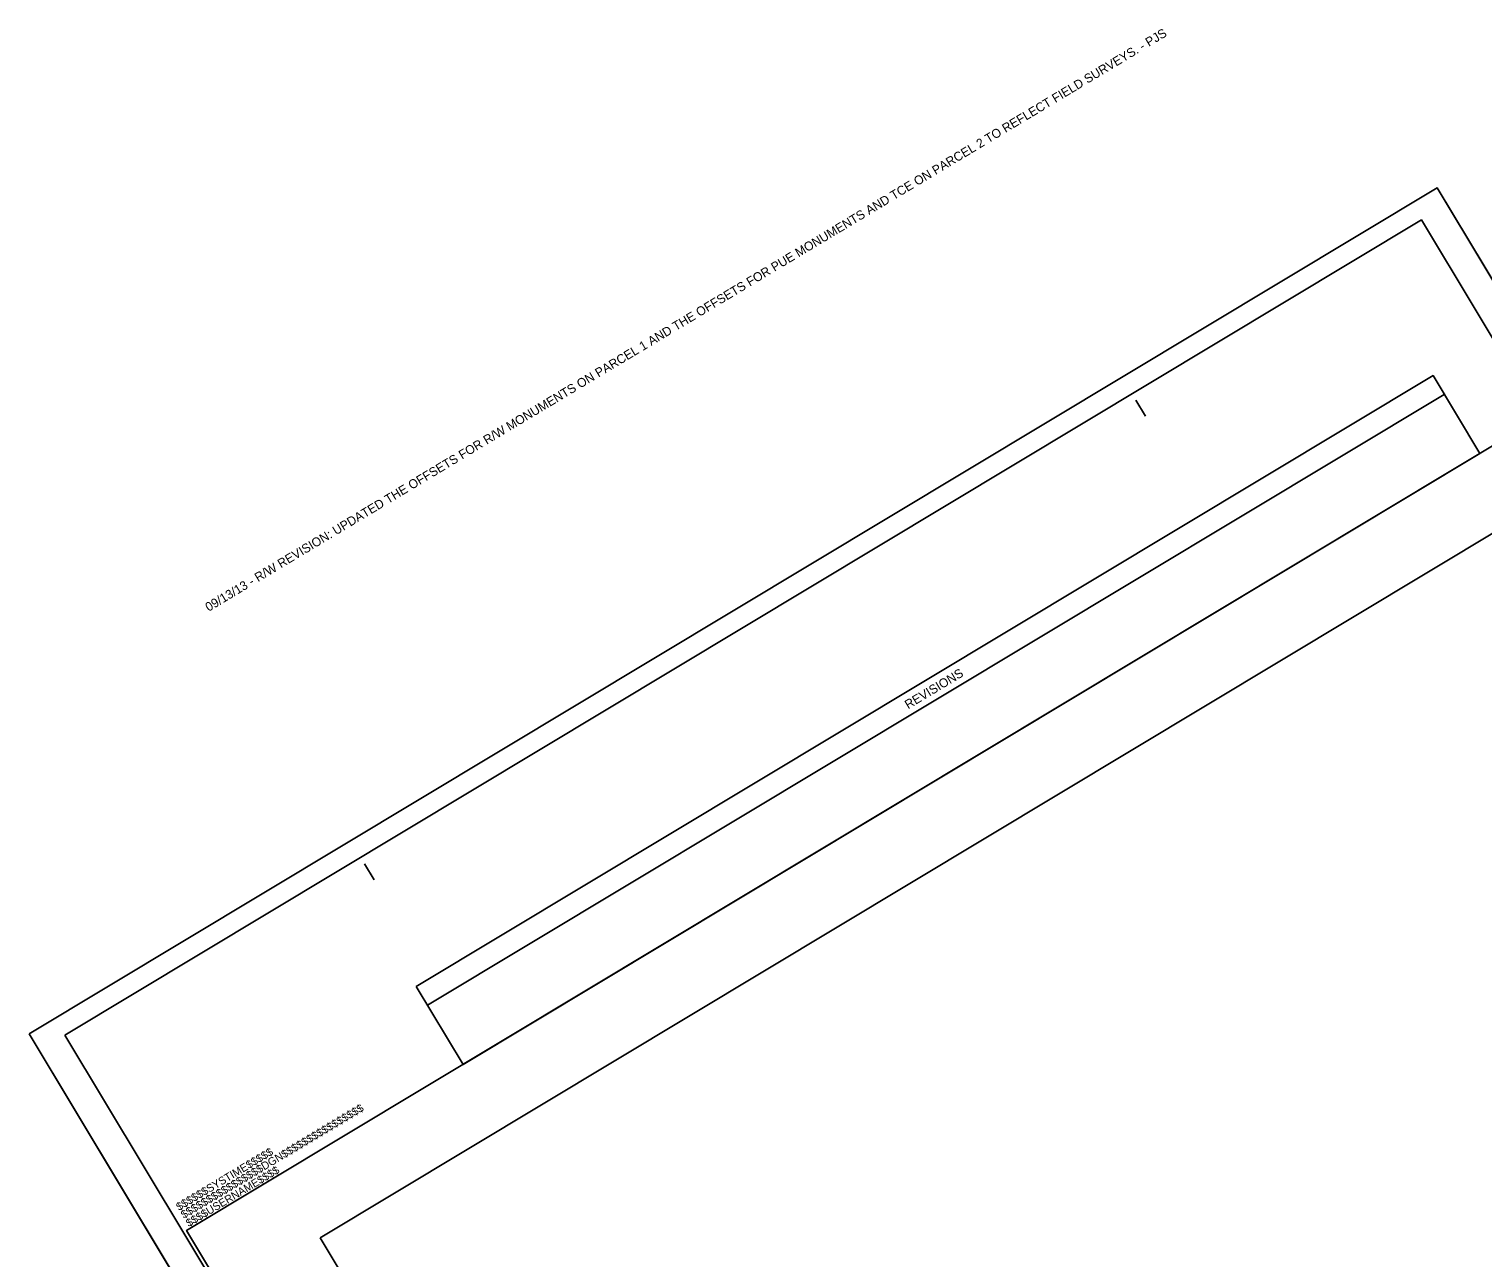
# Model space of a CAD drawing. Extents: x 1779635 to 1781473, y 814562 to 816692.
# Drawn here: x 1779635 to 1780604, y 815873 to 816692 of the extents above; entities that cross this region are included whole.
import ezdxf

# ---------------------------------------------------------------- set-up
doc = ezdxf.new("R2010")
doc.units = 0
for name, color, linetype in [('Sheet Block Revision CELL', 7, 'Continuous'), ('Sheet Clip Boundary CELL', 7, 'Continuous'), ('Sheet Cutting Line CELL', 7, 'Continuous'), ('Sheet Plan CELL', 7, 'Continuous'), ('Sheet Plan Layout CELL', 7, 'Continuous'), ('Sheet Plot Border Inside CELL', 7, 'Continuous'), ('Sheet Plot Border Outside CELL', 7, 'Continuous')]:
    doc.layers.add(name, color=color, linetype=linetype)

msp = doc.modelspace()

# ---------------------------------------------------------------- linework, layer by layer
at = {"layer": 'Sheet Block Revision CELL'}
msp.add_line((1779900.54, 816041.56), (1780578.24, 816448.78), dxfattribs=at)
msp.add_lwpolyline([(1779893.02, 816054.02), (1780570.74, 816461.24), (1780601.94, 816409.36), (1779924.22, 816002.14)], close=True, dxfattribs=at)
at = {"layer": 'Sheet Clip Boundary CELL'}
msp.add_lwpolyline([(1779828.88, 815886.54), (1780515.2, 814744.31), (1781170.74, 815138.2), (1781108.01, 815242.61), (1781289.29, 815351.54), (1780665.7, 816389.35)], close=True, dxfattribs=at)
at = {"layer": 'Sheet Cutting Line CELL'}
for p, q in [((1780573.48, 816586.5), (1779634.88, 816022.53)), ((1781440.55, 815143.46), (1780573.48, 816586.5)), ((1779634.88, 816022.53), (1780501.95, 814579.49))]:
    msp.add_line(p, q, dxfattribs=at)
at = {"layer": 'Sheet Plan CELL'}
for p, q in [((1780372.73, 816444.89), (1780379.19, 816434.18)), ((1779858.45, 816135.85), (1779864.88, 816125.13)), ((1779739.93, 815891.42), (1779739.93, 815891.42))]:
    msp.add_line(p, q, dxfattribs=at)
for points in [[(1779739.93, 815891.42), (1780639.92, 816432.22), (1781309.49, 815317.93), (1781180.87, 815240.63), (1781283.89, 815069.16), (1780512.49, 814605.66)], [(1781412.53, 815146.43), (1780639.95, 816432.21), (1779739.93, 815891.42), (1780512.49, 814605.66)]]:
    msp.add_lwpolyline(points, close=True, dxfattribs=at)
at = {"layer": 'Sheet Plan Layout CELL'}
msp.add_lwpolyline([(1780639.92, 816432.22), (1779739.93, 815891.42), (1780512.48, 814605.67), (1781231.23, 815037.54), (1781108.01, 815242.61), (1781289.29, 815351.54)], close=True, dxfattribs=at)
at = {"layer": 'Sheet Plot Border Inside CELL'}
msp.add_lwpolyline([(1779658.72, 816021.69), (1780516.78, 814593.67), (1781421.08, 815137.02), (1780563.03, 816565.06)], close=True, dxfattribs=at)
at = {"layer": 'Sheet Plot Border Outside CELL'}
msp.add_lwpolyline([(1779634.88, 816022.53), (1780501.95, 814579.49), (1781440.55, 815143.46), (1780573.48, 816586.5)], close=True, dxfattribs=at)

# ---------------------------------------------------------------- texts
at = {"layer": 'Sheet Block Revision CELL'}
for s, p in [('09/13/13 - R/W REVISION: UPDATED THE OFFSETS FOR R/W MONUMENTS ON PARCEL 1 AND THE OFFSETS FOR PUE MONUMENTS AND TCE ON PARCEL 2 TO REFLECT FIELD SURVEYS. - PJS', (1779754.6, 816303.78)), ('REVISIONS', (1780220.87, 816238.77))]:
    msp.add_text(s, height=6, rotation=31, dxfattribs=at).set_placement(p)
at = {"layer": 'Sheet Plan CELL'}
for s, p in [('$$$$$$$$$$$$$$$$DGN$$$$$$$$$$$$$$$$', (1779738.02, 815899.18)), ('$$$$$$SYSTIME$$$$$', (1779734.87, 815904.38)), ('$$$$USERNAME$$$$', (1779741.4, 815893.58))]:
    msp.add_text(s, height=5.25, rotation=31, dxfattribs=at).set_placement(p)

doc.saveas('drawing.dxf')
